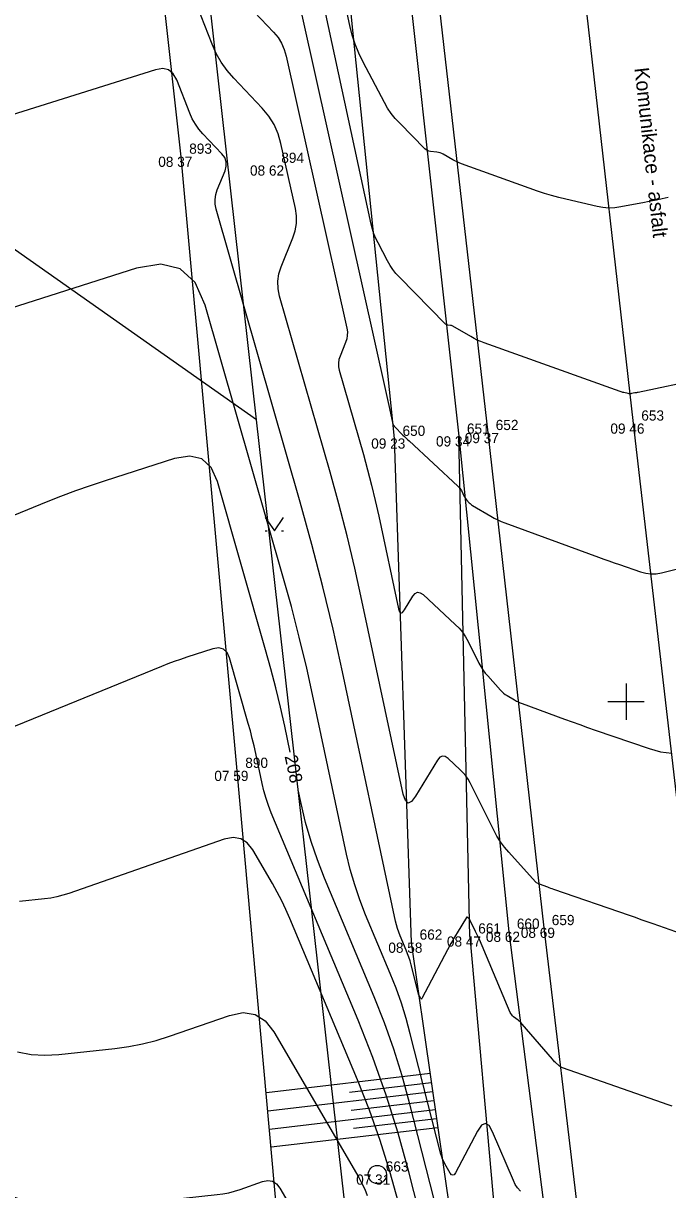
# Model space of a CAD drawing. Extents: x -711234 to -710007, y -1026313 to -1025448.
# Drawn here: x -710916.56 to -710898.86, y -1025963.41 to -1025931.37 of the extents above; entities that cross this region are included whole.
import ezdxf

# ---------------------------------------------------------------- set-up
doc = ezdxf.new("R2010")
doc.units = 0
for name, color, linetype in [('Ex_Contour Labels', 7, 'Continuous'), ('Ex_Major Contours', 7, 'Continuous'), ('Ex_Minor Contours', 7, 'Continuous'), ('Z_body', 7, 'Continuous'), ('Z_body_cisla', 7, 'Continuous'), ('Z_body_vysky_redukovane', 7, 'Continuous'), ('Z_hektometricka_sit', 7, 'Continuous'), ('Z_hrany_paty', 7, 'Continuous'), ('Z_katastr_hranice', 7, 'Continuous'), ('Z_komunikace', 7, 'Continuous'), ('Z_komunikace_osa', 7, 'Continuous'), ('Z_pole_rozhranni', 7, 'Continuous'), ('Z_popisy', 7, 'Continuous'), ('Z_rozhranni', 7, 'Continuous'), ('Z_technicke_srafy', 7, 'Continuous'), ('Z_vdz12_plna', 7, 'Continuous'), ('Z_vdz25_plna', 7, 'Continuous'), ('Z_zelen_jednotliva', 7, 'Continuous'), ('Z_znaky_kultur', 7, 'Continuous')]:
    doc.layers.add(name, color=color, linetype=linetype)

# ---------------------------------------------------------------- blocks, each defined once
blk = doc.blocks.new('POINT_DISPLAY')
blk.add_line((0, 0), (0, 0))
blk = doc.blocks.new('Z10001')
blk.add_circle((0, 0), 0.25)
blk = doc.blocks.new('Z314')
for p, q in [((-0.25, 0.17), (0, -0.2)), ((0, -0.2), (0.25, 0.17)), ((-0.25, -0.2), (-0.2, -0.2)), ((0.2, -0.2), (0.25, -0.2))]:
    blk.add_line(p, q)

msp = doc.modelspace()

# ---------------------------------------------------------------- linework, layer by layer
at = {"layer": 'Ex_Major Contours'}
for points in [[(-710910.209, -1025931.057), (-710909.681, -1025931.614), (-710909.56, -1025931.759), (-710909.462, -1025931.916), (-710909.387, -1025932.085), (-710909.334, -1025932.267), (-710907.67, -1025939.742), (-710907.655, -1025939.842), (-710907.656, -1025939.94), (-710907.672, -1025940.036), (-710907.703, -1025940.132), (-710907.857, -1025940.511), (-710907.888, -1025940.606), (-710907.901, -1025940.702), (-710907.898, -1025940.799), (-710907.878, -1025940.897), (-710907.214, -1025943.213), (-710907.098, -1025943.633), (-710906.989, -1025944.054), (-710906.887, -1025944.477), (-710906.793, -1025944.903), (-710906.25, -1025947.453), (-710906.223, -1025947.536), (-710906.186, -1025947.569), (-710906.141, -1025947.55), (-710906.088, -1025947.481), (-710905.856, -1025947.1), (-710905.795, -1025947.026), (-710905.729, -1025946.995), (-710905.656, -1025947.007), (-710905.577, -1025947.061), (-710904.69, -1025947.879), (-710904.587, -1025947.983), (-710904.494, -1025948.096), (-710904.412, -1025948.216), (-710904.34, -1025948.344), (-710904.039, -1025948.946), (-710903.988, -1025949.039), (-710903.931, -1025949.129), (-710903.869, -1025949.214), (-710903.8, -1025949.296), (-710903.451, -1025949.683), (-710903.41, -1025949.726), (-710903.366, -1025949.765), (-710903.319, -1025949.8), (-710903.269, -1025949.832), (-710903.064, -1025949.954), (-710903.013, -1025949.983), (-710902.96, -1025950.01), (-710902.906, -1025950.034), (-710902.85, -1025950.055), (-710901.693, -1025950.479), (-710901.481, -1025950.556), (-710901.269, -1025950.632), (-710901.056, -1025950.707), (-710900.844, -1025950.781), (-710899.368, -1025951.291), (-710899.055, -1025951.375), (-710898.741, -1025951.412)], [(-710909.225, -1025951.392), (-710909.377, -1025950.677), (-710909.494, -1025950.148), (-710909.621, -1025949.622), (-710909.756, -1025949.098), (-710909.901, -1025948.576), (-710911.226, -1025943.952), (-710911.398, -1025943.568), (-710911.651, -1025943.335), (-710911.985, -1025943.254), (-710912.401, -1025943.324), (-710914.313, -1025943.935), (-710914.722, -1025944.07), (-710915.128, -1025944.213), (-710915.531, -1025944.363), (-710915.931, -1025944.522), (-710917.527, -1025945.171)], [(-710904.465, -1025966.835), (-710905.945, -1025961.02), (-710906.148, -1025960.279), (-710906.378, -1025959.547), (-710906.635, -1025958.824), (-710906.919, -1025958.111), (-710908.282, -1025954.854), (-710908.479, -1025954.35), (-710908.652, -1025953.84), (-710908.801, -1025953.321), (-710908.926, -1025952.795), (-710909.006, -1025952.419)], [(-710926.145, -1025960.075), (-710916.837, -1025963.602), (-710916.269, -1025963.781), (-710915.691, -1025963.891), (-710915.105, -1025963.93), (-710914.51, -1025963.9), (-710911.236, -1025963.544), (-710911.075, -1025963.522), (-710910.915, -1025963.491), (-710910.757, -1025963.451), (-710910.601, -1025963.401), (-710909.982, -1025963.186), (-710909.837, -1025963.157), (-710909.709, -1025963.176), (-710909.6, -1025963.244), (-710909.508, -1025963.362), (-710908.812, -1025964.556), (-710908.677, -1025964.805), (-710908.557, -1025965.062), (-710908.453, -1025965.325), (-710908.365, -1025965.595), (-710906.758, -1025971.097)]]:
    msp.add_lwpolyline(points, dxfattribs=at)
at = {"layer": 'Ex_Minor Contours'}
for points in [[(-710898.84, -1025936.154), (-710899.003, -1025936.188), (-710899.166, -1025936.221), (-710899.329, -1025936.254), (-710899.492, -1025936.285), (-710900.145, -1025936.412), (-710900.308, -1025936.435), (-710900.471, -1025936.441), (-710900.633, -1025936.429), (-710900.795, -1025936.4), (-710901.653, -1025936.201), (-710901.85, -1025936.153), (-710902.044, -1025936.099), (-710902.237, -1025936.039), (-710902.428, -1025935.974), (-710904.52, -1025935.225), (-710904.582, -1025935.202), (-710904.642, -1025935.175), (-710904.702, -1025935.146), (-710904.759, -1025935.115), (-710905.024, -1025934.961), (-710905.064, -1025934.94), (-710905.105, -1025934.924), (-710905.148, -1025934.913), (-710905.193, -1025934.905), (-710905.373, -1025934.886), (-710905.416, -1025934.877), (-710905.456, -1025934.862), (-710905.493, -1025934.84), (-710905.527, -1025934.811), (-710906.218, -1025934.11), (-710906.339, -1025933.979), (-710906.449, -1025933.84), (-710906.549, -1025933.693), (-710906.638, -1025933.538), (-710907.223, -1025932.43), (-710907.34, -1025932.19), (-710907.44, -1025931.943), (-710907.522, -1025931.689), (-710907.588, -1025931.43), (-710908.524, -1025927.091)], [(-710898.322, -1025956.431), (-710899.258, -1025956.103), (-710899.419, -1025956.046), (-710899.58, -1025955.99), (-710899.741, -1025955.934), (-710899.902, -1025955.879), (-710901.986, -1025955.159), (-710902.027, -1025955.145), (-710902.068, -1025955.13), (-710902.109, -1025955.116), (-710902.15, -1025955.101), (-710902.374, -1025955.019), (-710902.385, -1025955.015), (-710902.395, -1025955.01), (-710902.406, -1025955.005), (-710902.416, -1025954.999), (-710902.455, -1025954.976), (-710902.465, -1025954.969), (-710902.474, -1025954.963), (-710902.483, -1025954.955), (-710902.49, -1025954.947), (-710903.219, -1025954.138), (-710903.338, -1025953.997), (-710903.447, -1025953.849), (-710903.545, -1025953.693), (-710903.633, -1025953.531), (-710904.285, -1025952.232), (-710904.34, -1025952.133), (-710904.403, -1025952.04), (-710904.474, -1025951.954), (-710904.554, -1025951.873), (-710904.889, -1025951.564), (-710904.97, -1025951.509), (-710905.044, -1025951.497), (-710905.112, -1025951.529), (-710905.175, -1025951.605), (-710905.781, -1025952.601), (-710905.893, -1025952.746), (-710905.987, -1025952.785), (-710906.062, -1025952.717), (-710906.12, -1025952.543), (-710907.253, -1025947.221), (-710907.45, -1025946.333), (-710907.662, -1025945.45), (-710907.89, -1025944.57), (-710908.132, -1025943.694), (-710909.517, -1025938.86), (-710909.559, -1025938.656), (-710909.565, -1025938.454), (-710909.537, -1025938.253), (-710909.474, -1025938.055), (-710909.152, -1025937.264), (-710909.087, -1025937.065), (-710909.054, -1025936.863), (-710909.053, -1025936.659), (-710909.083, -1025936.452), (-710909.48, -1025934.669), (-710909.558, -1025934.4), (-710909.67, -1025934.15), (-710909.815, -1025933.917), (-710909.994, -1025933.702), (-710910.775, -1025932.878), (-710910.959, -1025932.665), (-710911.12, -1025932.437), (-710911.258, -1025932.194), (-710911.373, -1025931.937), (-710912.681, -1025928.594)], [(-710896.203, -1025940.775), (-710899.668, -1025941.504), (-710899.69, -1025941.509), (-710899.713, -1025941.513), (-710899.735, -1025941.518), (-710899.757, -1025941.522), (-710899.848, -1025941.54), (-710899.87, -1025941.543), (-710899.892, -1025941.544), (-710899.915, -1025941.542), (-710899.937, -1025941.538), (-710900.056, -1025941.51), (-710900.083, -1025941.504), (-710900.11, -1025941.496), (-710900.136, -1025941.488), (-710900.163, -1025941.479), (-710903.898, -1025940.143), (-710903.993, -1025940.107), (-710904.085, -1025940.067), (-710904.176, -1025940.022), (-710904.264, -1025939.973), (-710904.759, -1025939.686), (-710904.775, -1025939.678), (-710904.791, -1025939.672), (-710904.808, -1025939.667), (-710904.825, -1025939.664), (-710904.895, -1025939.657), (-710904.912, -1025939.653), (-710904.928, -1025939.647), (-710904.942, -1025939.639), (-710904.955, -1025939.628), (-710906.226, -1025938.34), (-710906.32, -1025938.237), (-710906.406, -1025938.129), (-710906.483, -1025938.015), (-710906.552, -1025937.894), (-710906.813, -1025937.401), (-710906.874, -1025937.276), (-710906.925, -1025937.148), (-710906.968, -1025937.017), (-710907.002, -1025936.882), (-710908.798, -1025928.562)], [(-710909.188, -1025929.864), (-710906.59, -1025941.538), (-710906.572, -1025941.62), (-710906.554, -1025941.701), (-710906.536, -1025941.783), (-710906.518, -1025941.864), (-710906.417, -1025942.334), (-710906.414, -1025942.344), (-710906.411, -1025942.354), (-710906.407, -1025942.363), (-710906.403, -1025942.372), (-710906.384, -1025942.409), (-710906.378, -1025942.418), (-710906.373, -1025942.426), (-710906.366, -1025942.434), (-710906.359, -1025942.442), (-710906.128, -1025942.676), (-710906.087, -1025942.717), (-710906.045, -1025942.758), (-710906.003, -1025942.798), (-710905.961, -1025942.838), (-710904.616, -1025944.078), (-710904.589, -1025944.106), (-710904.565, -1025944.136), (-710904.543, -1025944.167), (-710904.524, -1025944.201), (-710904.444, -1025944.361), (-710904.431, -1025944.385), (-710904.416, -1025944.409), (-710904.399, -1025944.432), (-710904.381, -1025944.453), (-710904.305, -1025944.537), (-710904.286, -1025944.557), (-710904.265, -1025944.576), (-710904.242, -1025944.593), (-710904.219, -1025944.608), (-710903.713, -1025944.908), (-710903.62, -1025944.961), (-710903.524, -1025945.009), (-710903.426, -1025945.053), (-710903.326, -1025945.092), (-710900.757, -1025946.032), (-710900.614, -1025946.085), (-710900.47, -1025946.136), (-710900.327, -1025946.187), (-710900.183, -1025946.237), (-710899.603, -1025946.437), (-710899.46, -1025946.475), (-710899.316, -1025946.492), (-710899.172, -1025946.488), (-710899.026, -1025946.462), (-710898.442, -1025946.315)], [(-710898.73, -1025961.112), (-710898.866, -1025961.067), (-710899.001, -1025961.02), (-710901.746, -1025960.059), (-710901.775, -1025960.047), (-710901.801, -1025960.033), (-710901.826, -1025960.016), (-710901.849, -1025959.997), (-710901.939, -1025959.913), (-710901.961, -1025959.892), (-710901.983, -1025959.87), (-710902.003, -1025959.847), (-710902.024, -1025959.824), (-710902.854, -1025958.856), (-710902.88, -1025958.827), (-710902.907, -1025958.8), (-710902.935, -1025958.774), (-710902.965, -1025958.75), (-710903.088, -1025958.656), (-710903.116, -1025958.631), (-710903.141, -1025958.603), (-710903.162, -1025958.571), (-710903.179, -1025958.537), (-710904.027, -1025956.539), (-710904.052, -1025956.482), (-710904.078, -1025956.425), (-710904.104, -1025956.368), (-710904.132, -1025956.312), (-710904.289, -1025955.998), (-710904.295, -1025955.987), (-710904.302, -1025955.978), (-710904.31, -1025955.968), (-710904.318, -1025955.96), (-710904.354, -1025955.927), (-710904.363, -1025955.921), (-710904.371, -1025955.919), (-710904.378, -1025955.923), (-710904.385, -1025955.931), (-710904.64, -1025956.35), (-710904.684, -1025956.423), (-710904.727, -1025956.498), (-710904.769, -1025956.573), (-710904.809, -1025956.648), (-710905.606, -1025958.154), (-710905.614, -1025958.166), (-710905.623, -1025958.17), (-710905.631, -1025958.166), (-710905.64, -1025958.155), (-710905.676, -1025958.094), (-710905.684, -1025958.078), (-710905.691, -1025958.062), (-710905.697, -1025958.046), (-710905.702, -1025958.029), (-710905.906, -1025957.227), (-710905.934, -1025957.125), (-710905.966, -1025957.024), (-710906.001, -1025956.924), (-710906.041, -1025956.826), (-710906.204, -1025956.434), (-710906.243, -1025956.336), (-710906.277, -1025956.236), (-710906.306, -1025956.134), (-710906.33, -1025956.031), (-710907.788, -1025949.185), (-710908.048, -1025948.012), (-710908.329, -1025946.844), (-710908.63, -1025945.681), (-710908.951, -1025944.523), (-710911.258, -1025936.471), (-710911.285, -1025936.336), (-710911.29, -1025936.202), (-710911.271, -1025936.07), (-710911.229, -1025935.939), (-710911.016, -1025935.416), (-710910.982, -1025935.289), (-710910.985, -1025935.169), (-710911.025, -1025935.056), (-710911.104, -1025934.95), (-710911.622, -1025934.403), (-710911.734, -1025934.274), (-710911.831, -1025934.135), (-710911.915, -1025933.988), (-710911.985, -1025933.831), (-710912.341, -1025932.922), (-710912.437, -1025932.751), (-710912.566, -1025932.648), (-710912.728, -1025932.612), (-710912.922, -1025932.644), (-710918.329, -1025934.339)], [(-710902.901, -1025963.445), (-710902.977, -1025963.358), (-710903.042, -1025963.262), (-710903.094, -1025963.157), (-710903.664, -1025961.814), (-710903.761, -1025961.646), (-710903.862, -1025961.587), (-710903.968, -1025961.637), (-710904.078, -1025961.796), (-710904.687, -1025962.947), (-710904.722, -1025962.996), (-710904.757, -1025963.012), (-710904.792, -1025962.997), (-710904.829, -1025962.95), (-710904.975, -1025962.699), (-710905.009, -1025962.635), (-710905.038, -1025962.569), (-710905.063, -1025962.501), (-710905.084, -1025962.432), (-710905.926, -1025959.123), (-710906.041, -1025958.702), (-710906.172, -1025958.285), (-710906.318, -1025957.874), (-710906.48, -1025957.468), (-710907.155, -1025955.854), (-710907.315, -1025955.447), (-710907.454, -1025955.034), (-710907.575, -1025954.616), (-710907.676, -1025954.191), (-710908.582, -1025949.931), (-710908.771, -1025949.08), (-710908.975, -1025948.233), (-710909.193, -1025947.39), (-710909.426, -1025946.55), (-710911.559, -1025939.105), (-710911.836, -1025938.487), (-710912.244, -1025938.113), (-710912.782, -1025937.982), (-710913.45, -1025938.094), (-710917.555, -1025939.406)], [(-710903.847, -1025971.238), (-710905.965, -1025962.916), (-710906.256, -1025961.856), (-710906.585, -1025960.809), (-710906.952, -1025959.774), (-710907.358, -1025958.753), (-710909.744, -1025953.053), (-710909.821, -1025952.856), (-710909.889, -1025952.657), (-710909.947, -1025952.455), (-710909.995, -1025952.249), (-710910.172, -1025951.423), (-710910.217, -1025951.216), (-710910.267, -1025951.011), (-710910.32, -1025950.807), (-710910.376, -1025950.603), (-710910.893, -1025948.798), (-710910.96, -1025948.648), (-710911.059, -1025948.558), (-710911.189, -1025948.526), (-710911.351, -1025948.553), (-710912.062, -1025948.78), (-710912.24, -1025948.839), (-710912.416, -1025948.901), (-710912.59, -1025948.966), (-710912.764, -1025949.035), (-710917.241, -1025950.856)], [(-710906.251, -1025963.763), (-710906.487, -1025962.905), (-710906.753, -1025962.058), (-710907.05, -1025961.221), (-710907.379, -1025960.394), (-710909.235, -1025955.961), (-710909.343, -1025955.715), (-710909.458, -1025955.473), (-710909.582, -1025955.234), (-710909.713, -1025955), (-710910.255, -1025954.07), (-710910.406, -1025953.878), (-710910.586, -1025953.766), (-710910.795, -1025953.734), (-710911.035, -1025953.782), (-710915.306, -1025955.268), (-710915.47, -1025955.32), (-710915.636, -1025955.362), (-710915.804, -1025955.395), (-710915.974, -1025955.418), (-710916.66, -1025955.493)], [(-710916.716, -1025959.62), (-710916.344, -1025959.69), (-710915.967, -1025959.716), (-710915.585, -1025959.696), (-710914.042, -1025959.529), (-710913.659, -1025959.476), (-710913.281, -1025959.402), (-710912.907, -1025959.307), (-710912.539, -1025959.19), (-710910.893, -1025958.618), (-710910.519, -1025958.542), (-710910.192, -1025958.592), (-710909.911, -1025958.767), (-710909.677, -1025959.067), (-710907.34, -1025963.076), (-710907.254, -1025963.234), (-710907.178, -1025963.397), (-710907.112, -1025963.564)]]:
    msp.add_lwpolyline(points, dxfattribs=at)
at = {"layer": 'Z_hektometricka_sit'}
for p, q in [((-710900, -1025949.5), (-710900, -1025950.5)), ((-710900.5, -1025950), (-710899.5, -1025950))]:
    msp.add_line(p, q, dxfattribs=at)
at = {"layer": 'Z_hrany_paty'}
for p, q in [((-710908.26, -1025924.26), (-710906.37, -1025942.77)), ((-710906.37, -1025942.77), (-710905.9, -1025956.62)), ((-710905.9, -1025956.62), (-710903.24, -1025975.2))]:
    msp.add_line(p, q, dxfattribs=at)
at = {"layer": 'Z_katastr_hranice'}
for q in [(-710916.27, -1025887.83), (-710973.48, -1025897.7)]:
    msp.add_line((-710910.15, -1025942.26), q, dxfattribs=at)
msp.add_lwpolyline([(-710903.02, -1026002.95), (-710907.6, -1025964.93), (-710910.15, -1025942.26)], dxfattribs=at)
at = {"layer": 'Z_komunikace'}
for p, q in [((-710906.57, -1025924.94), (-710904.59, -1025942.71)), ((-710904.59, -1025942.71), (-710903.22, -1025956.32)), ((-710903.22, -1025956.32), (-710900.85, -1025974.9))]:
    msp.add_line(p, q, dxfattribs=at)
at = {"layer": 'Z_komunikace_osa'}
for p, q in [((-710901.86, -1025924.3), (-710899.8, -1025942.36)), ((-710899.8, -1025942.36), (-710898.24, -1025955.88))]:
    msp.add_line(p, q, dxfattribs=at)
at = {"layer": 'Z_pole_rozhranni'}
for p, q in [((-710912.22, -1025935.03), (-710913.93, -1025919.73)), ((-710910.68, -1025951.9), (-710912.22, -1025935.03)), ((-710909.4, -1025966.11), (-710910.68, -1025951.9))]:
    msp.add_line(p, q, dxfattribs=at)
at = {"layer": 'Z_rozhranni'}
for q in [(-710904.59, -1025942.71), (-710902.64, -1025975.01)]:
    msp.add_line((-710904.29, -1025956.45), q, dxfattribs=at)
at = {"layer": 'Z_technicke_srafy'}
for p, q in [((-710905.38, -1025960.22), (-710909.88, -1025960.75)), ((-710905.35, -1025960.47), (-710907.6, -1025960.74)), ((-710905.31, -1025960.72), (-710909.84, -1025961.25)), ((-710905.28, -1025960.97), (-710907.55, -1025961.23)), ((-710905.24, -1025961.21), (-710909.79, -1025961.75)), ((-710905.21, -1025961.46), (-710907.49, -1025961.73)), ((-710905.17, -1025961.71), (-710909.75, -1025962.24))]:
    msp.add_line(p, q, dxfattribs=at)
at = {"layer": 'Z_vdz12_plna'}
for p, q in [((-710903.8, -1025942.62), (-710902.26, -1025956.21)), ((-710902.26, -1025956.21), (-710900.03, -1025974.95))]:
    msp.add_line(p, q, dxfattribs=at)
at = {"layer": 'Z_vdz25_plna'}
msp.add_line((-710905.69, -1025925.98), (-710903.8, -1025942.62), dxfattribs=at)

# ---------------------------------------------------------------- block references
at = {"layer": 'Z_body'}
for p in [(-710912.22, -1025935.03), (-710909.7, -1025935.27), (-710899.8, -1025942.36), (-710904.59, -1025942.71), (-710903.8, -1025942.62), (-710906.37, -1025942.77), (-710910.68, -1025951.9), (-710902.26, -1025956.21), (-710904.29, -1025956.45), (-710903.22, -1025956.32), (-710905.9, -1025956.62), (-710906.83, -1025962.99)]:
    msp.add_blockref('POINT_DISPLAY', p, dxfattribs=at)
at = {"layer": 'Z_zelen_jednotliva'}
msp.add_blockref('Z10001', (-710906.83, -1025962.99), dxfattribs=at)
at = {"layer": 'Z_znaky_kultur'}
msp.add_blockref('Z314', (-710909.66, -1025945.11), dxfattribs=at)

# ---------------------------------------------------------------- texts
at = {"layer": 'Ex_Contour Labels'}
msp.add_text('208', height=0.35, rotation=282.0186, dxfattribs=at).set_placement((-710909.381, -1025951.5))
at = {"layer": 'Z_body_cisla'}
for s, p in [('893', (-710912, -1025934.95)), ('894', (-710909.47, -1025935.2)), ('653', (-710899.58, -1025942.28)), ('650', (-710906.14, -1025942.7)), ('651', (-710904.37, -1025942.64)), ('652', (-710903.58, -1025942.54)), ('890', (-710910.46, -1025951.82)), ('659', (-710902.04, -1025956.14)), ('661', (-710904.06, -1025956.37)), ('660', (-710903, -1025956.24)), ('662', (-710905.67, -1025956.54)), ('663', (-710906.6, -1025962.91))]:
    msp.add_text(s, height=0.28, dxfattribs=at).set_placement(p)
at = {"layer": 'Z_body_vysky_redukovane'}
for s, p in [('08 37', (-710912.85, -1025935.31)), ('08 62', (-710910.33, -1025935.55)), ('09 46', (-710900.43, -1025942.64)), ('09 34', (-710905.22, -1025942.99)), ('09 37', (-710904.43, -1025942.9)), ('09 23', (-710907, -1025943.05)), ('07 59', (-710911.31, -1025952.18)), ('08 69', (-710902.89, -1025956.49)), ('08 47', (-710904.92, -1025956.73)), ('08 62', (-710903.85, -1025956.6)), ('08 58', (-710906.53, -1025956.9)), ('07 31', (-710907.413, -1025963.27))]:
    msp.add_text(s, height=0.28, dxfattribs=at).set_placement(p)
at = {"layer": 'Z_popisy'}
msp.add_text('Komunikace - asfalt', height=0.4, rotation=276.3, dxfattribs=at).set_placement((-710899.77, -1025932.6))

doc.saveas('drawing.dxf')
